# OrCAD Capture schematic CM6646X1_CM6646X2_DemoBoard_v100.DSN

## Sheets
1 01.HISTORY NOTE: title: HISTORY NOTE; rev: v100; company: C-MEDIA ELECTRONICS Inc.; note: CMA162A EVB; note: 6F., 100, Sec. 4, Civil Boulevard, Taipei, Taiwan, R.O.C.
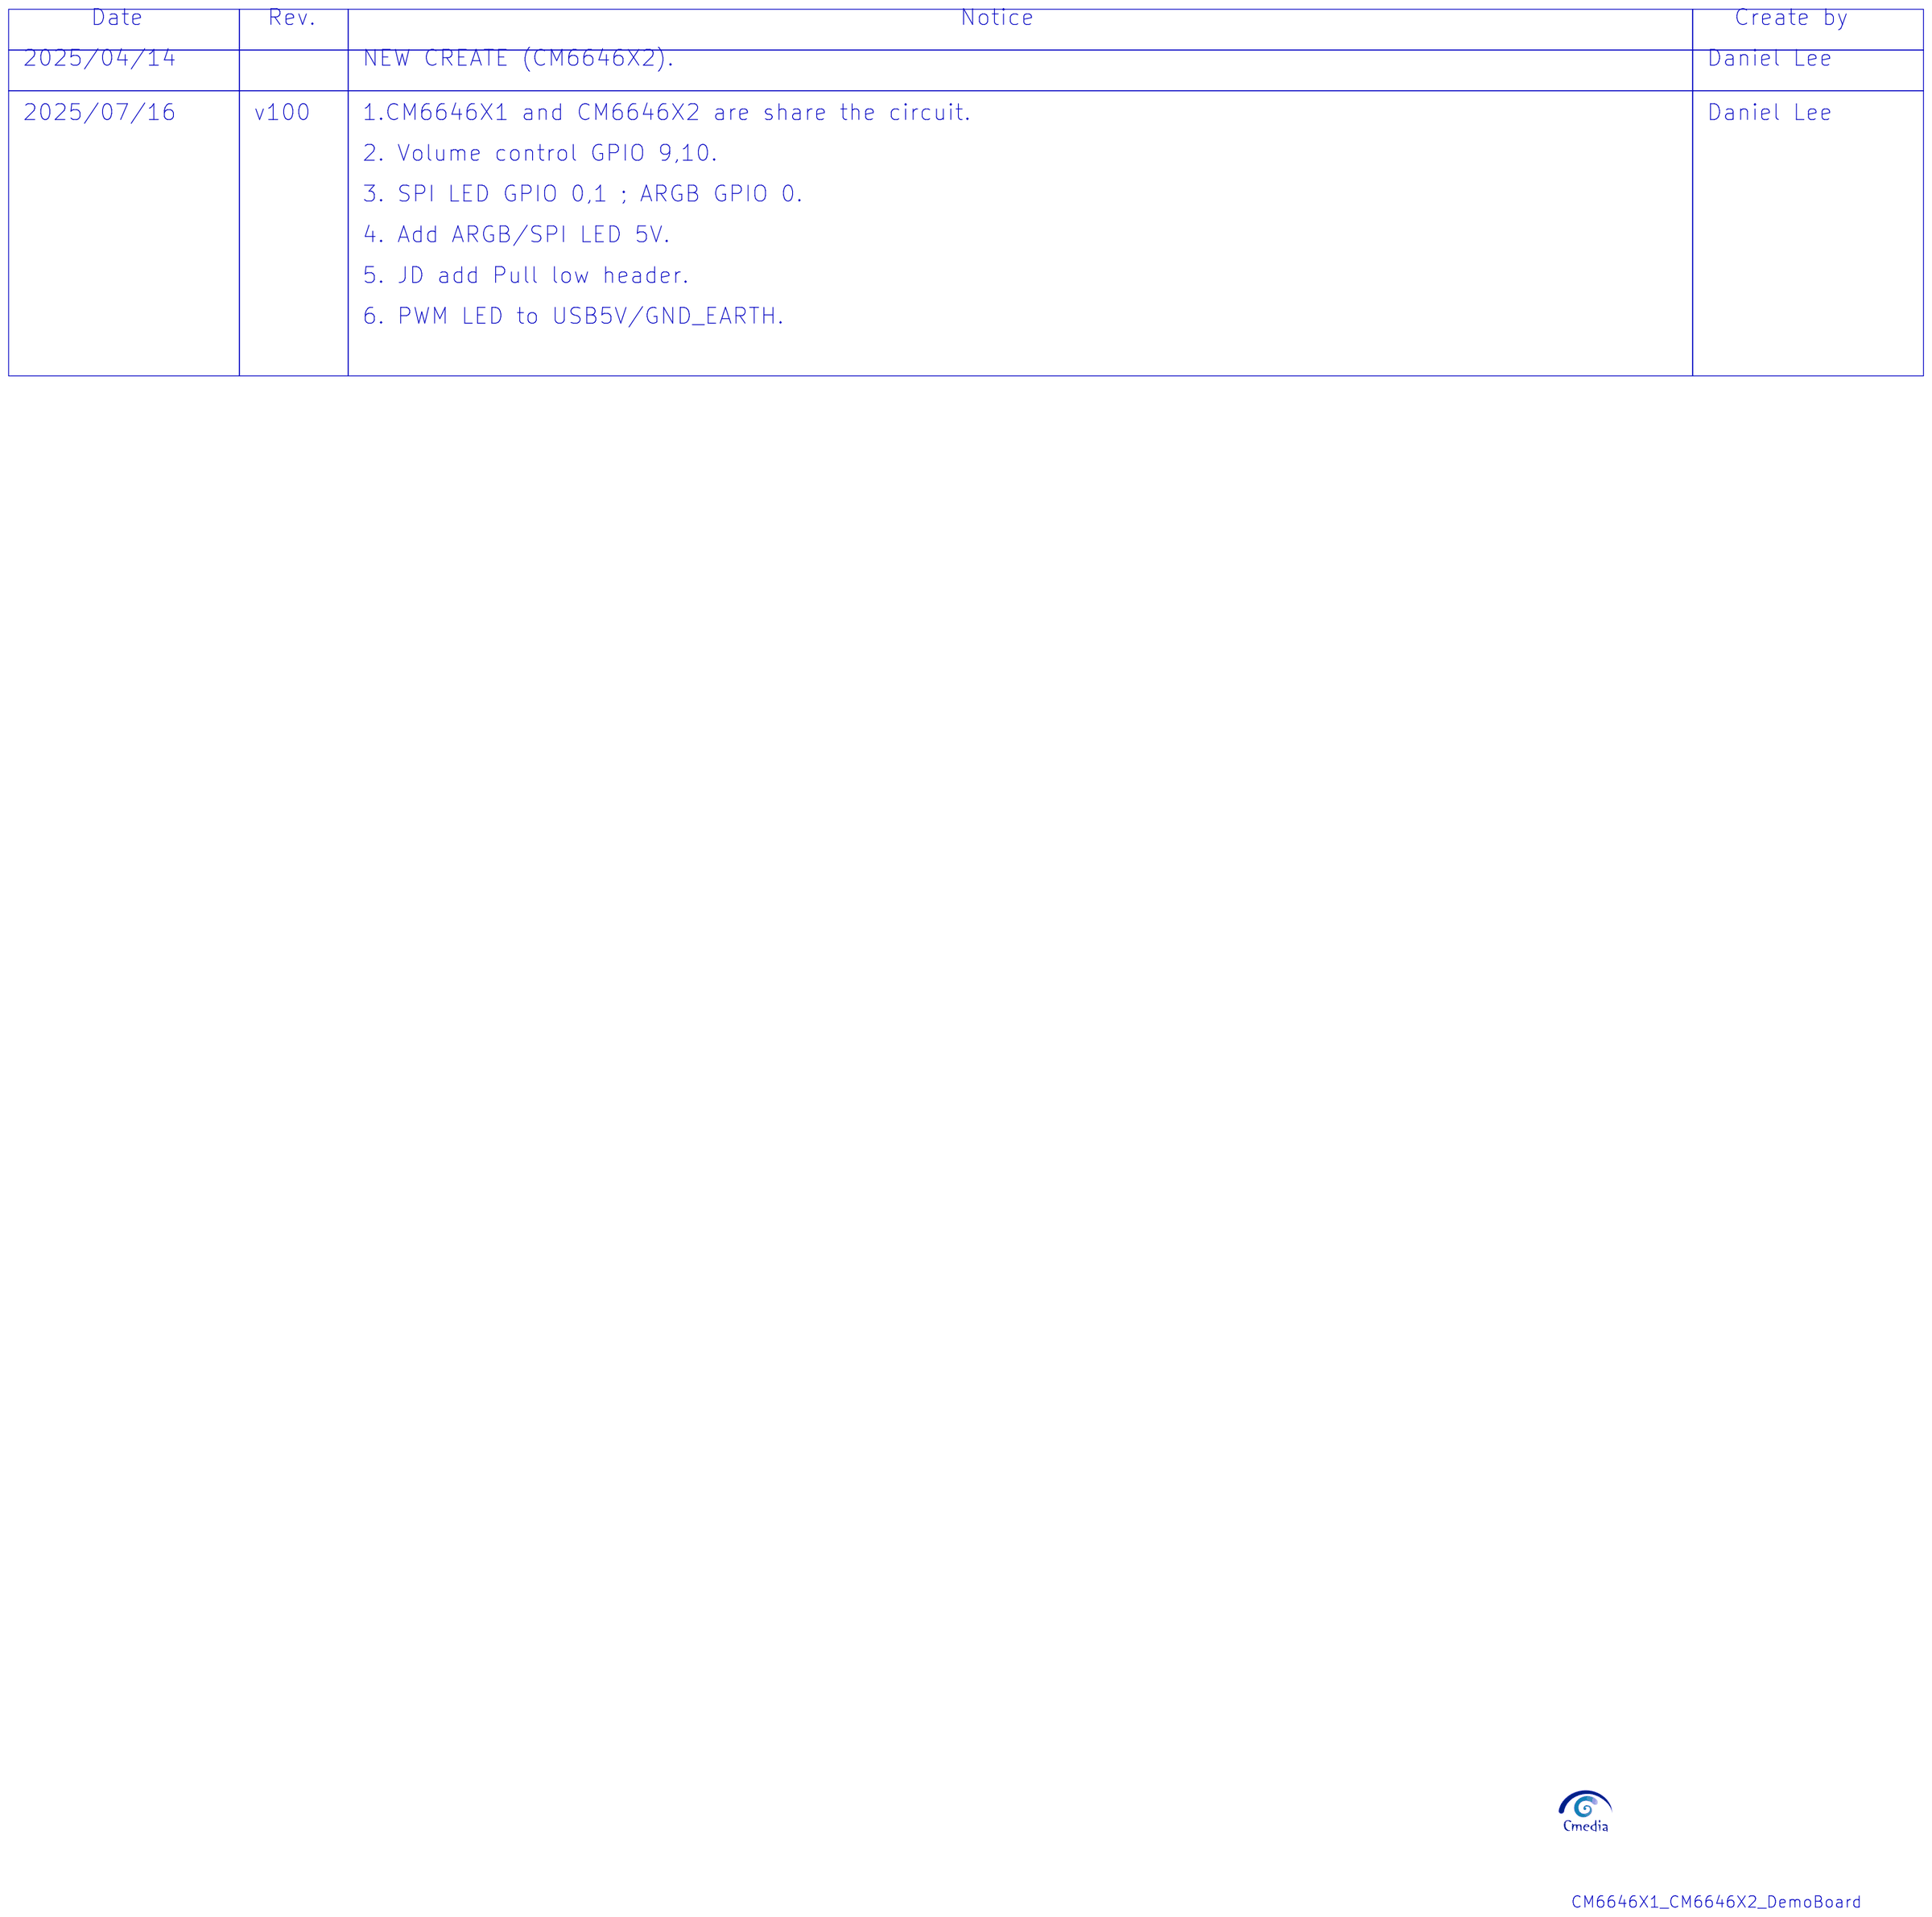
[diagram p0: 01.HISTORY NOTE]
2 02.FUNCTIONAL BLOCK DIAGRAM: title: CM6646X1_CM6646X2 DB FUNCTIONAL BLOCK
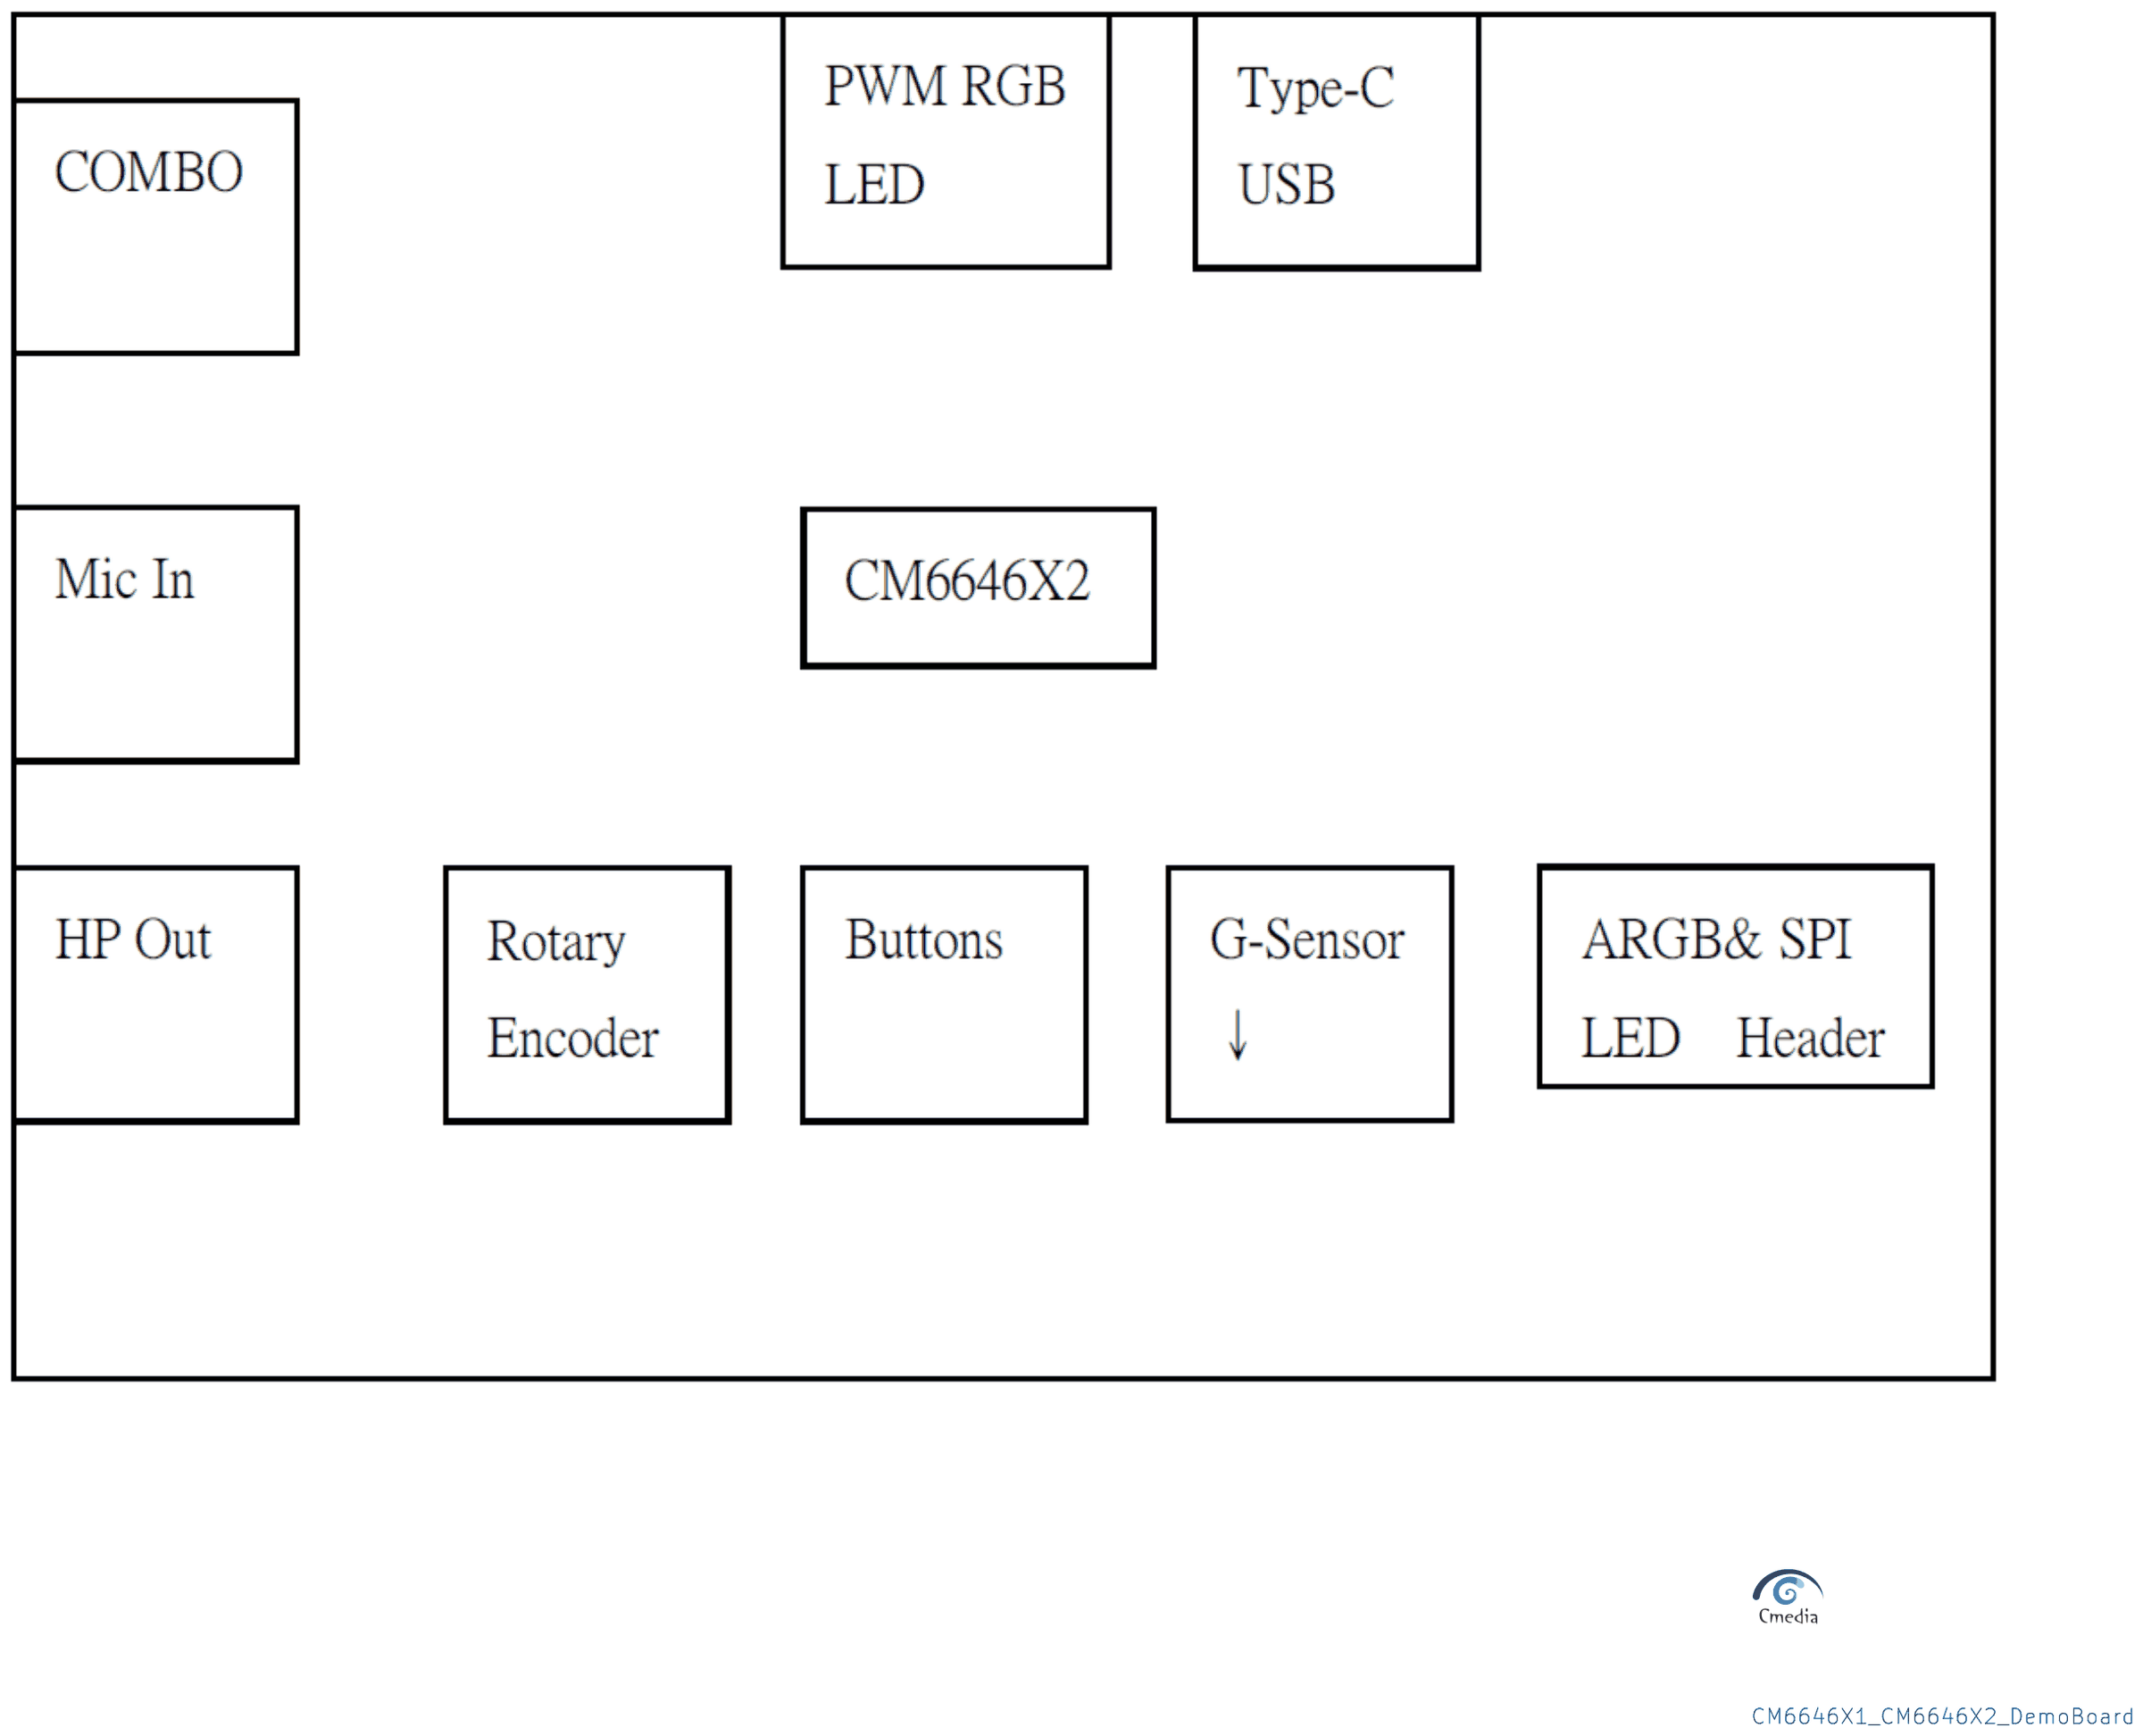
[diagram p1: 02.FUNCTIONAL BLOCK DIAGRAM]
3 03.PLACEMENT: title: Layout Placement
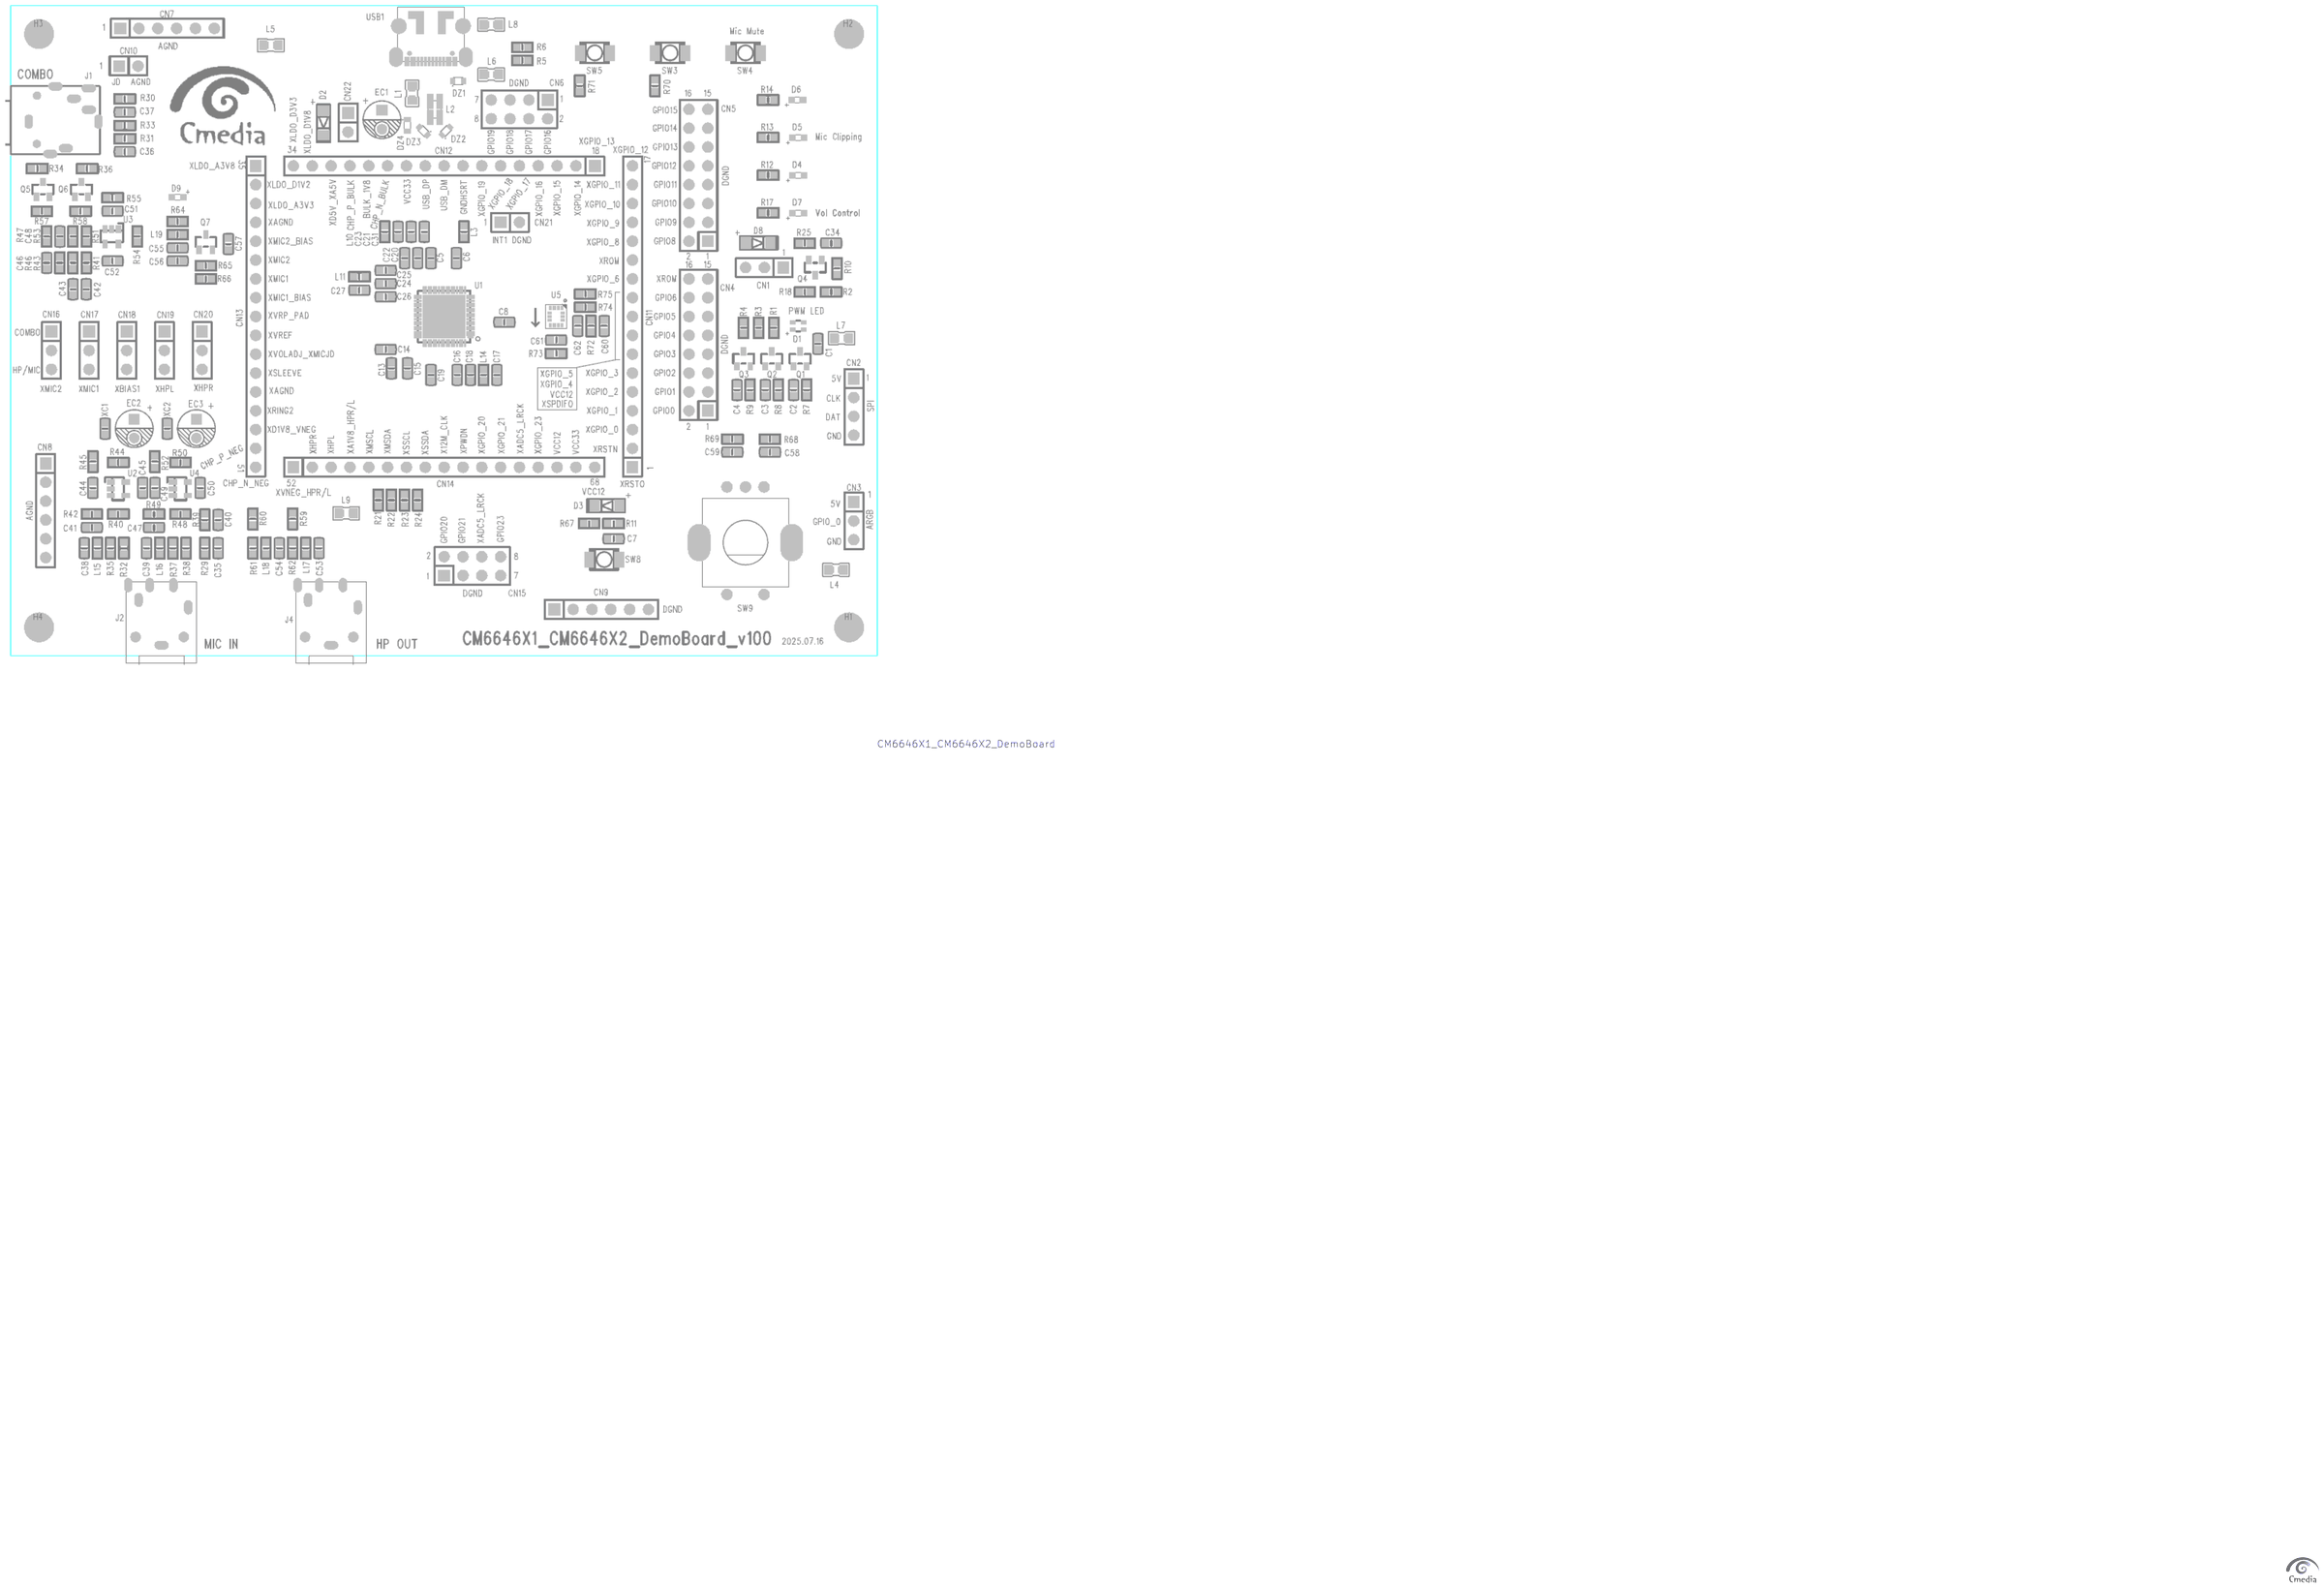
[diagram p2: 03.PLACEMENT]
4 04.CM6646X1_CM6646X2: size Custom; title: CM6646X1_CM6646X2 QFN-68; rev: v101
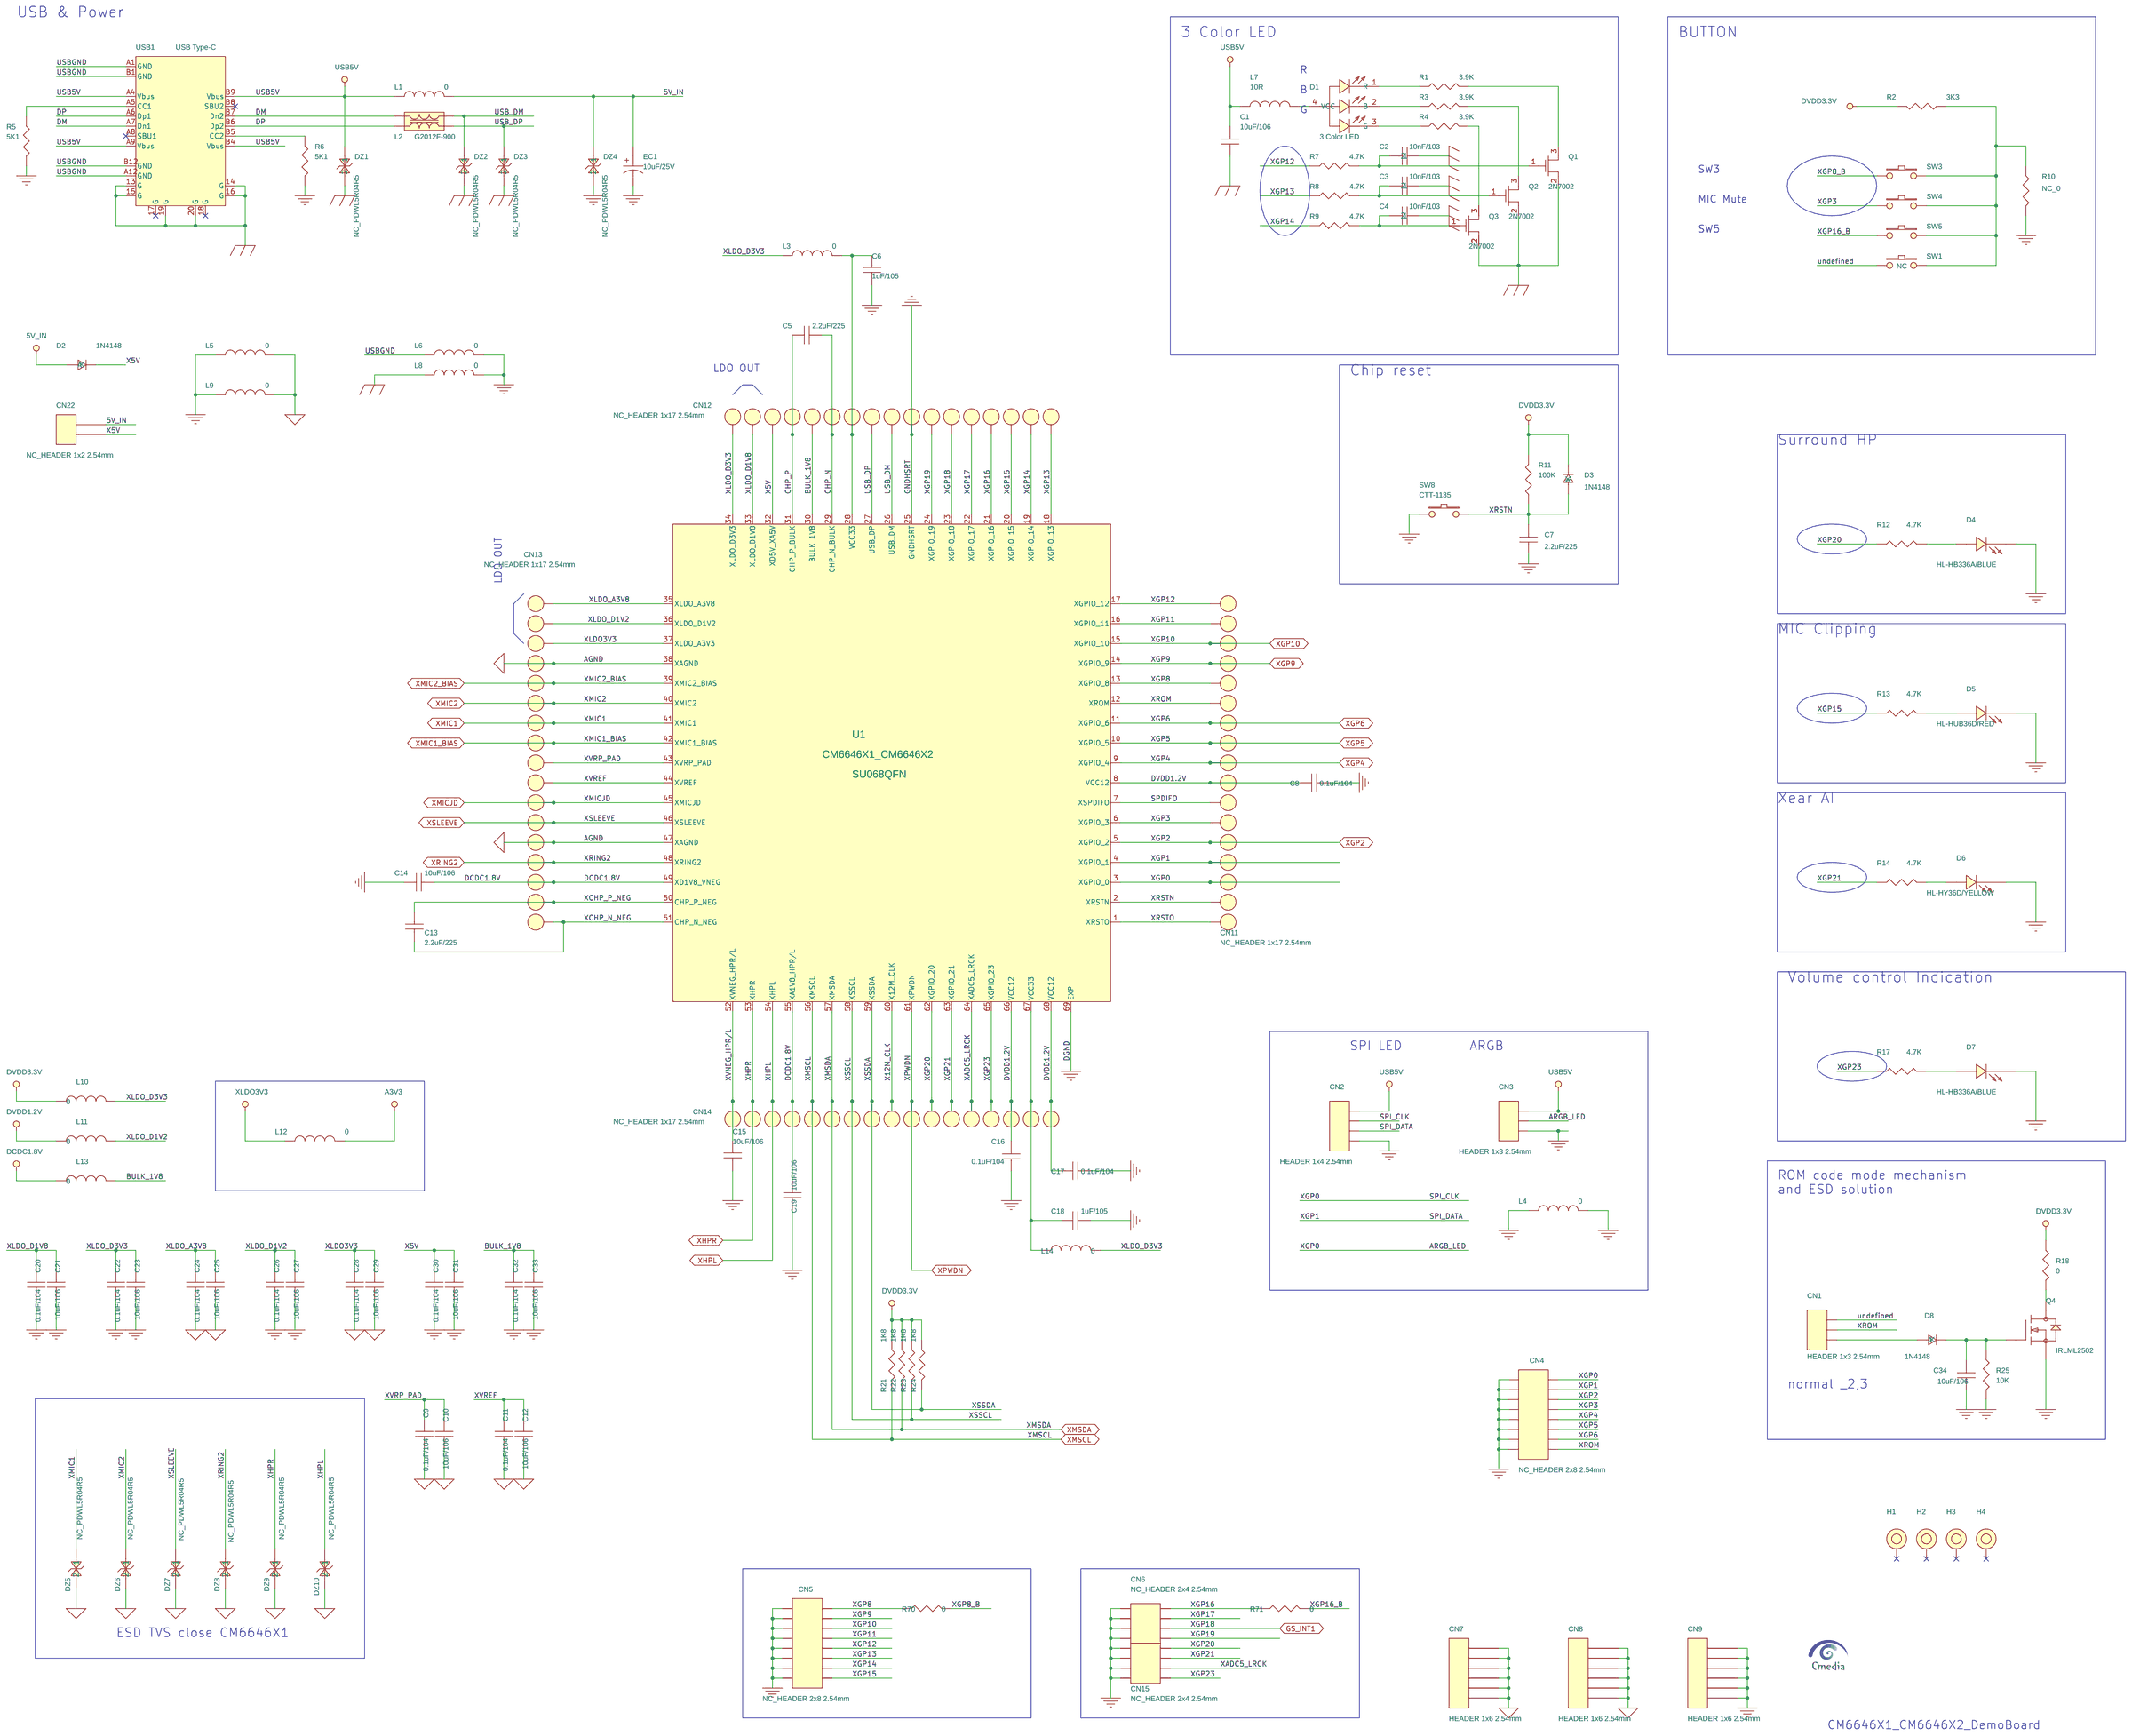
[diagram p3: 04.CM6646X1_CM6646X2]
5 05.G-Sensor: size A4; title: G-Sensor; note: CM6646X1_CM6646X2_DemoBoard
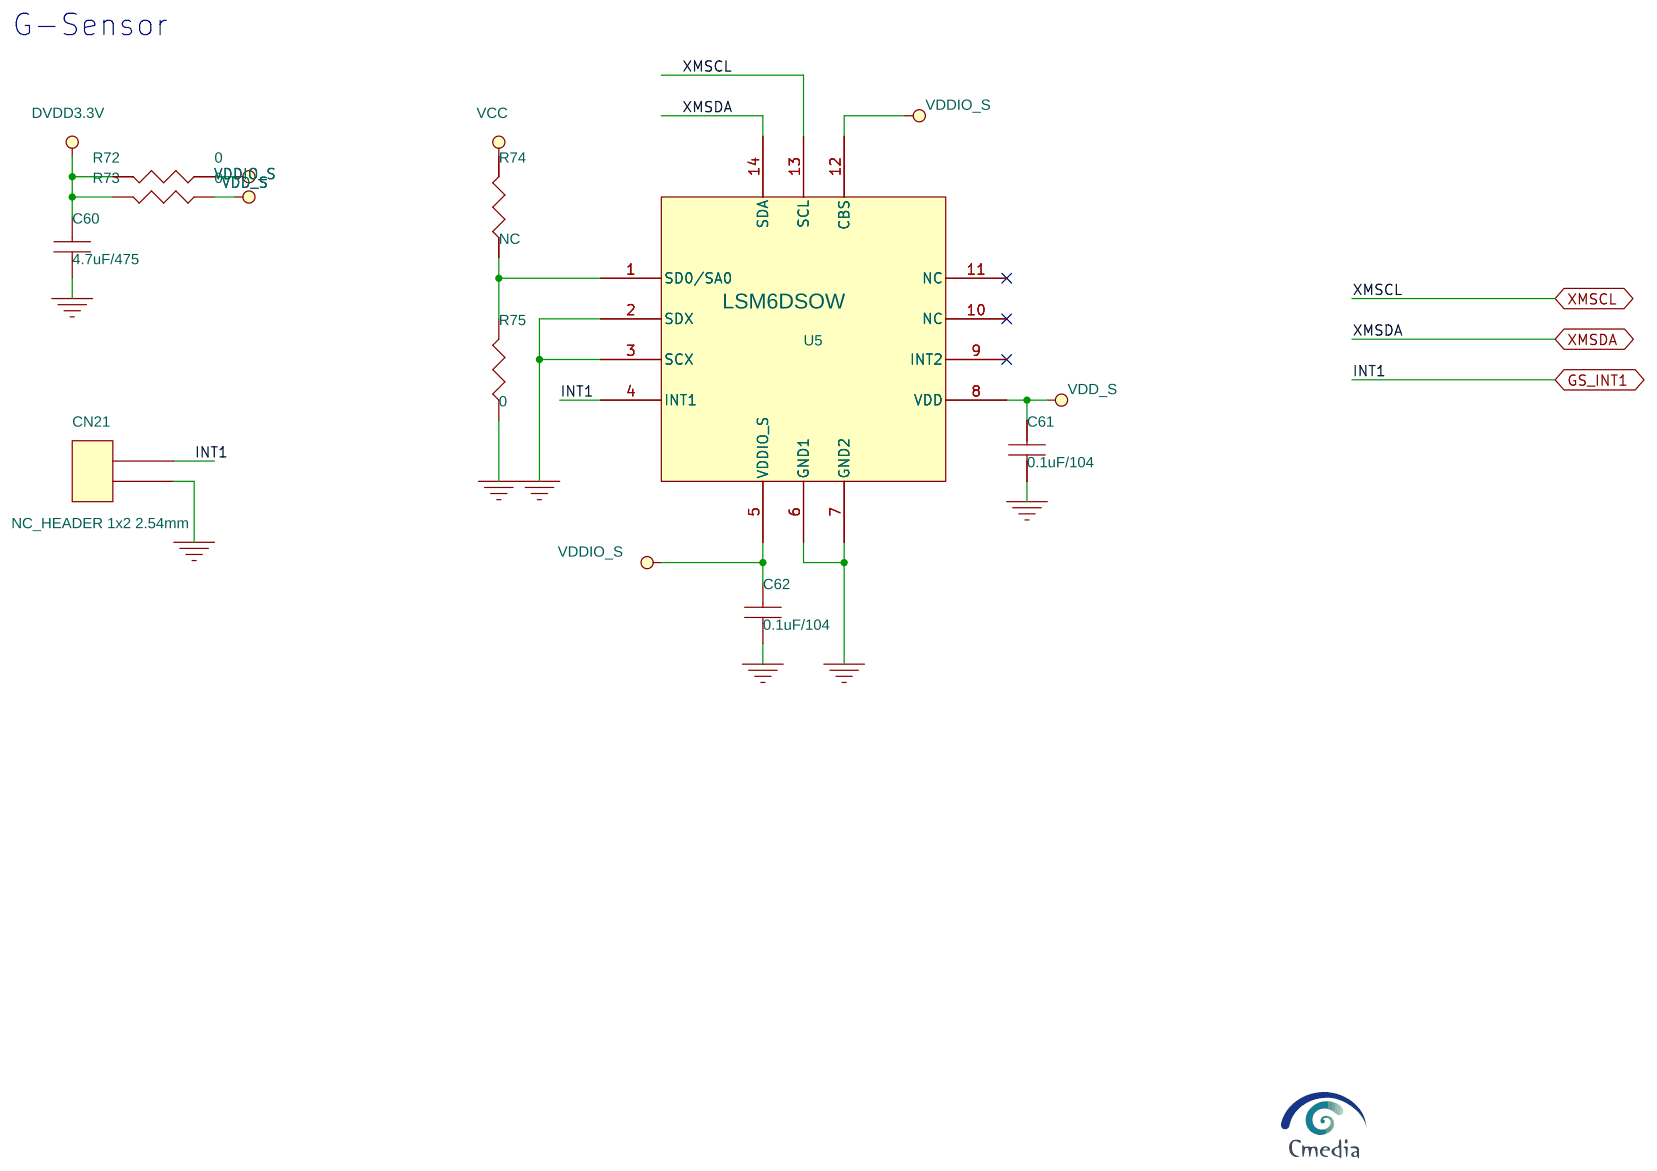
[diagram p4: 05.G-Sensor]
6 07.POWER: size B; title: OPA power and Encoder; rev: V100
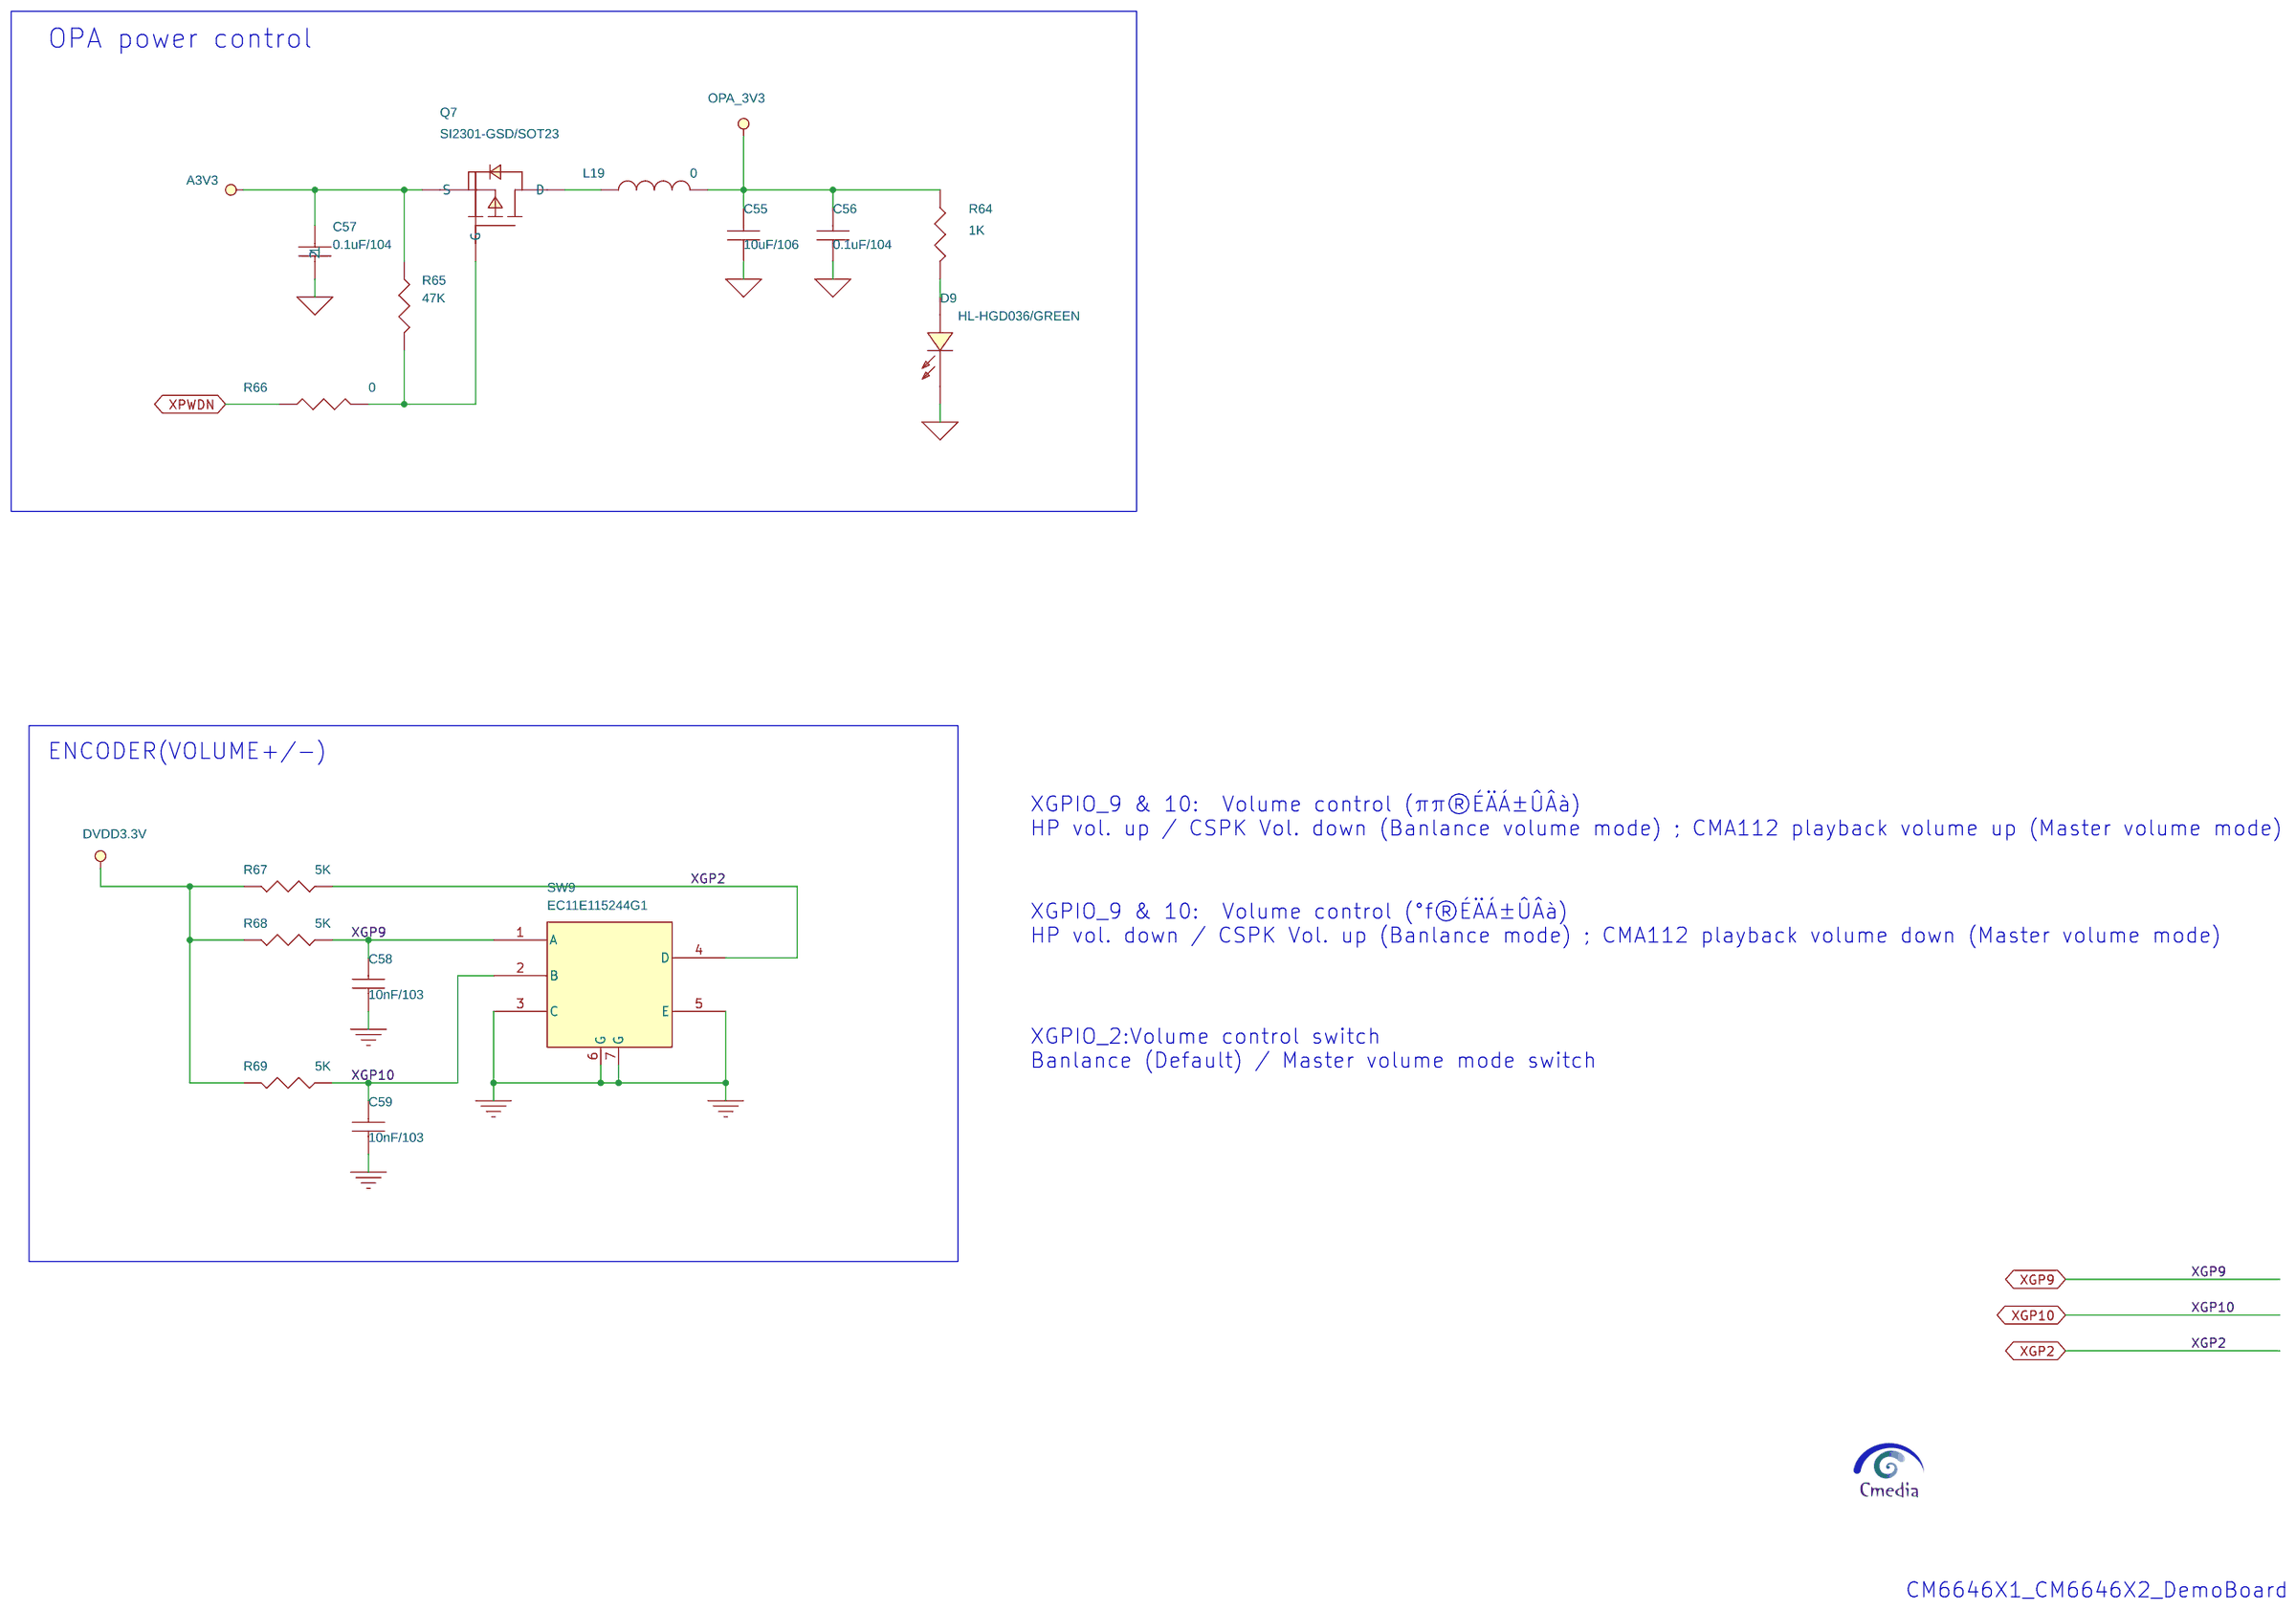
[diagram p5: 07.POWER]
7 06.ANALOG IN/OUT &COMBO JACK: size Custom; title: ANALOG IN/OUT &COMBO JACK; note: CM6646X1 Demoboard 68pin
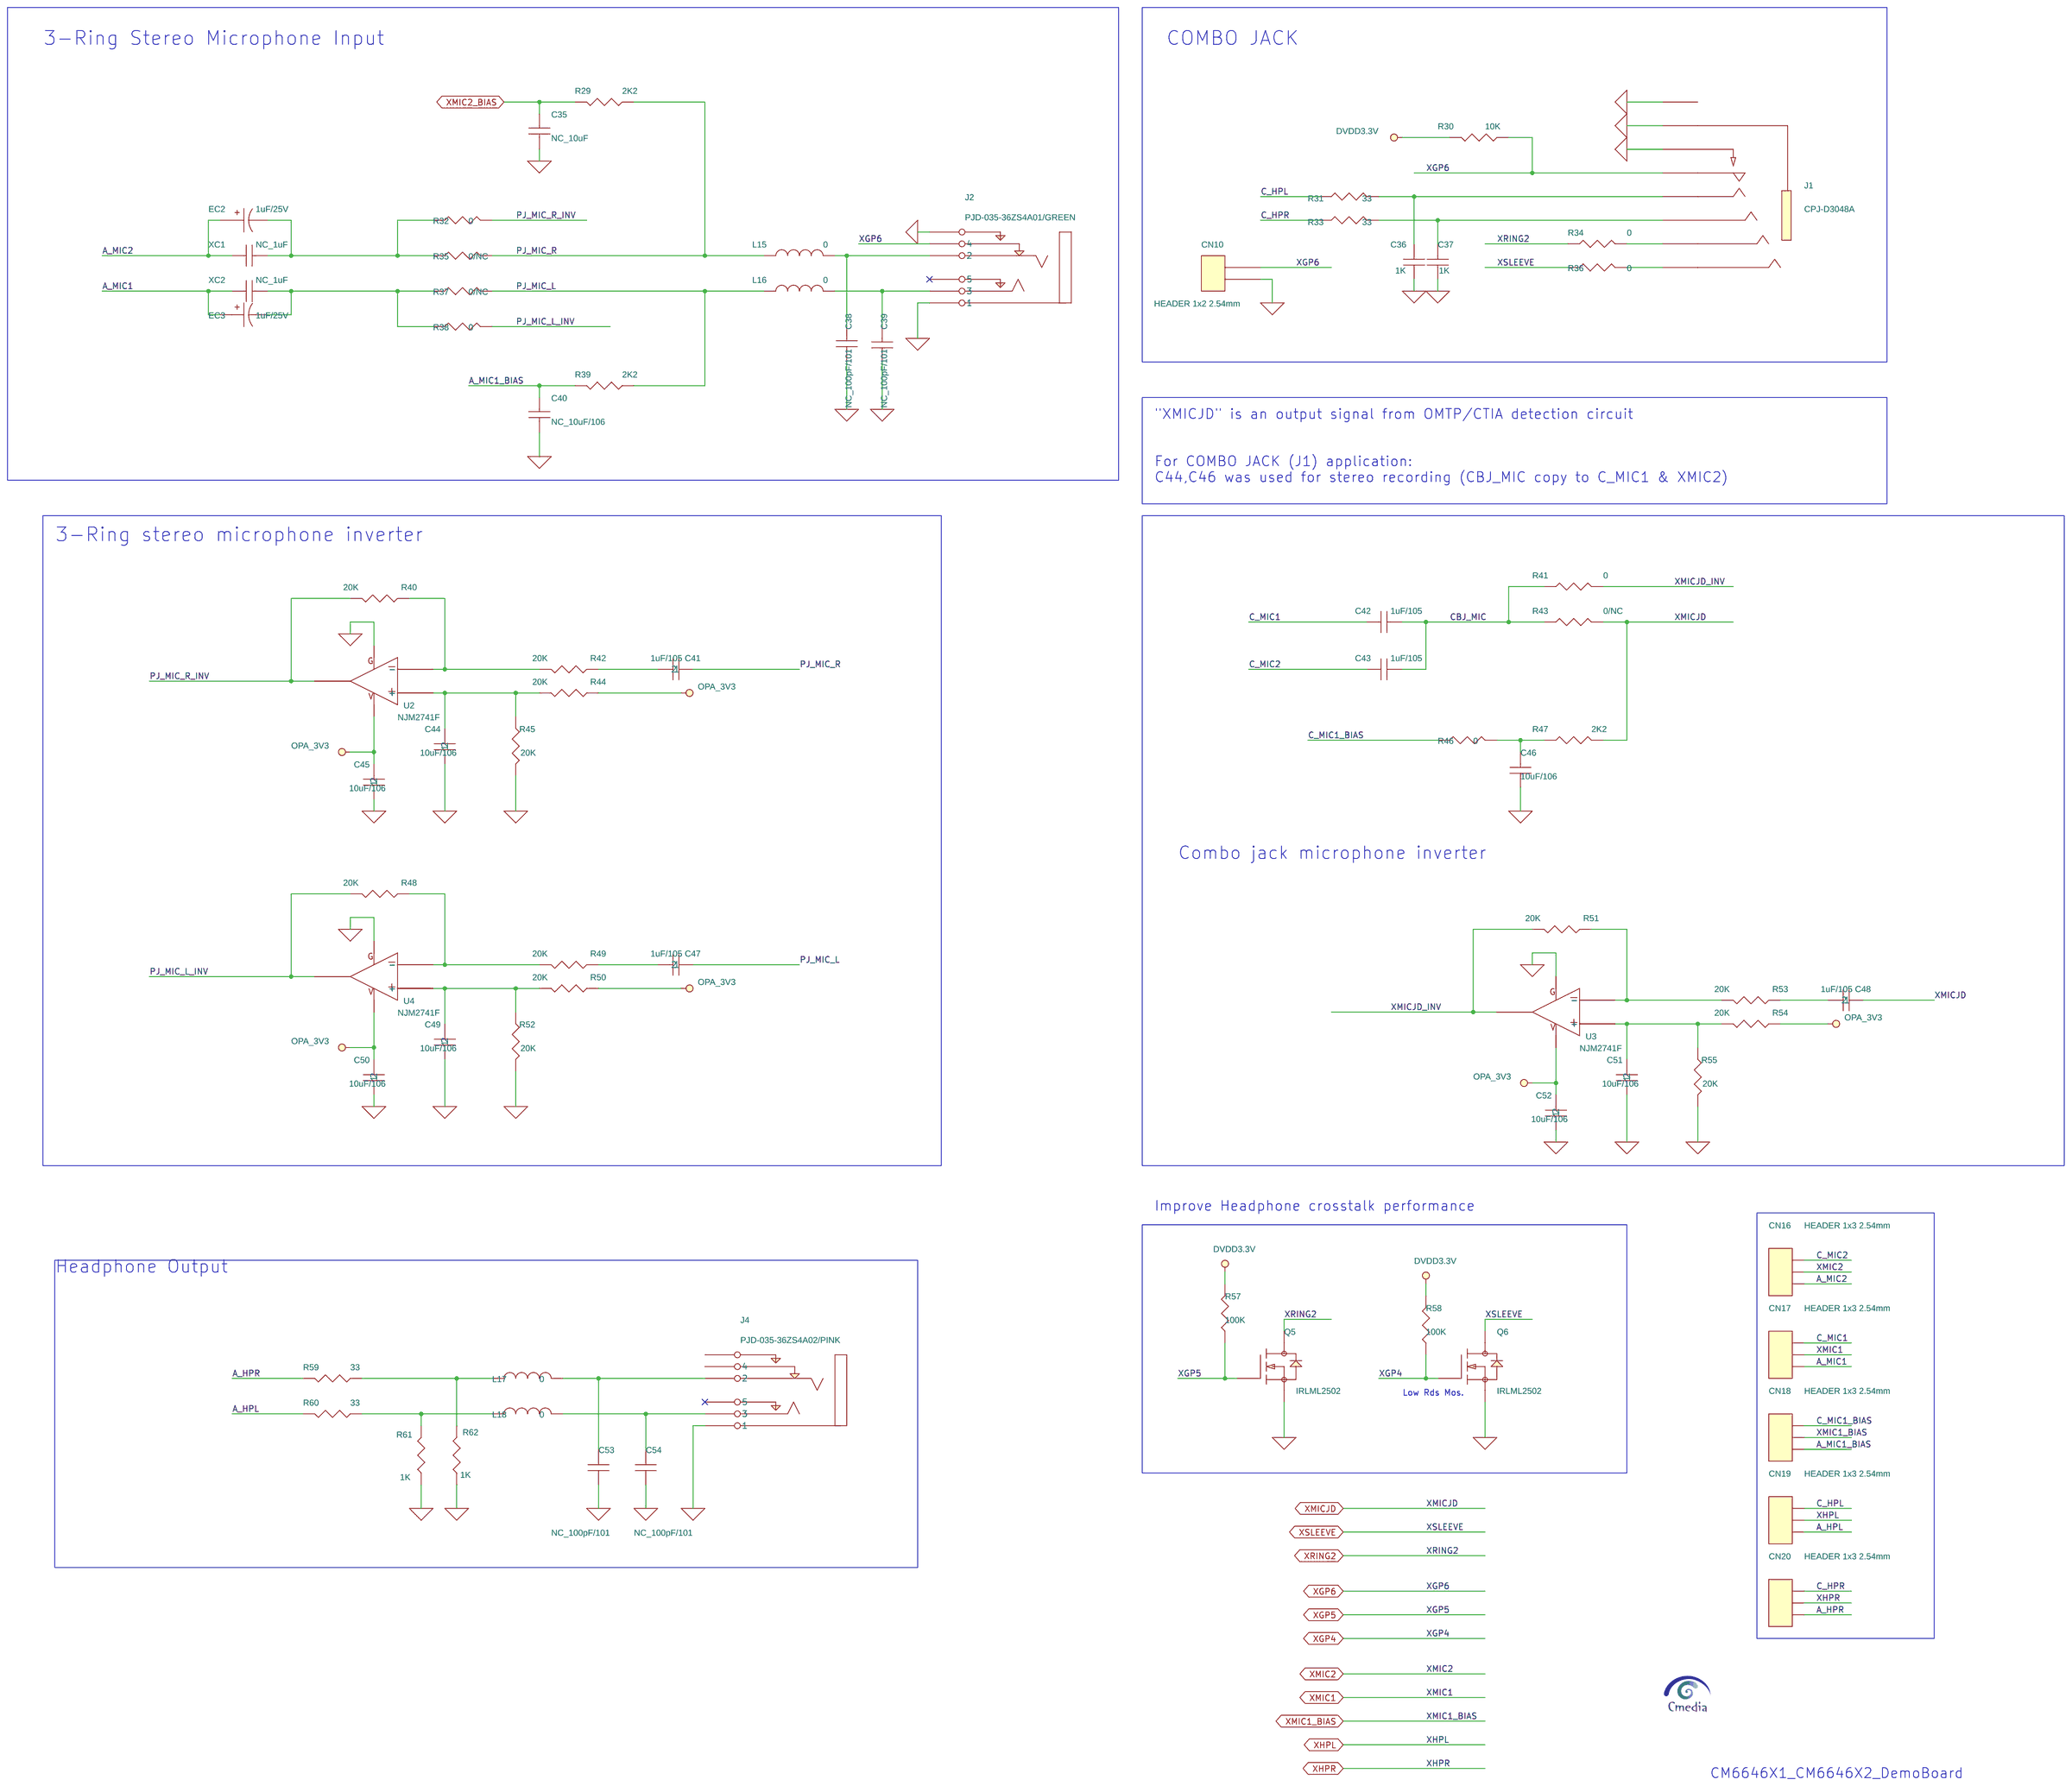
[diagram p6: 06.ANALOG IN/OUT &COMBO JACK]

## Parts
sheet 04.CM6646X1_CM6646X2
C1  10uF/106  [SC0603]
C2  10nF/103  [SC0603]
C3  10nF/103  [SC0603]
C4  10nF/103  [SC0603]
C5  2.2uF/225  [SC0603]
C6  1uF/105  [SC0603]
C7  2.2uF/225  [SC0603]
C8  0.1uF/104  [SC0603]
C9  0.1uF/104  [SC0603]
C10  10uF/106  [SC0603]
C11  0.1uF/104  [SC0603]
C12  10uF/106  [SC0603]
C13  2.2uF/225  [SC0603]
C14  10uF/106  [SC0603]
C15  10uF/106  [SC0603]
C16  0.1uF/104  [SC0603]
C17  0.1uF/104  [SC0603]
C18  1uF/105  [SC0603]
C19  10uF/106  [SC0603]
C20  0.1uF/104  [SC0603]
C21  10uF/106  [SC0603]
C22  0.1uF/104  [SC0603]
C23  10uF/106  [SC0603]
C24  0.1uF/104  [SC0603]
C25  10uF/106  [SC0603]
C26  0.1uF/104  [SC0603]
C27  10uF/106  [SC0603]
C28  0.1uF/104  [SC0603]
C29  10uF/106  [SC0603]
C30  0.1uF/104  [SC0603]
C31  10uF/106  [SC0603]
C32  0.1uF/104  [SC0603]
C33  10uF/106  [SC0603]
C34  10uF/106  [SC0603]
CN1  HEADER 1x3 2.54mm  [J1A3]
CN2  HEADER 1x4 2.54mm  [J1A4]
CN3  HEADER 1x3 2.54mm  [J1A3]
CN4  NC_HEADER 2x8 2.54mm  [J2A8A]
CN5  NC_HEADER 2x8 2.54mm  [J2A8A]
CN6  NC_HEADER 2x4 2.54mm  [J2A4A]
CN7  HEADER 1x6 2.54mm  [J1A6]
CN8  HEADER 1x6 2.54mm  [J1A6]
CN9  HEADER 1x6 2.54mm  [J1A6]
CN11  NC_HEADER 1x17 2.54mm  [J1A17]
CN12  NC_HEADER 1x17 2.54mm  [J1A17]
CN13  NC_HEADER 1x17 2.54mm  [J1A17]
CN14  NC_HEADER 1x17 2.54mm  [J1A17]
CN15  NC_HEADER 2x4 2.54mm  [J2A4A]
CN22  NC_HEADER 1x2 2.54mm  [J1A2]
D1  3 Color LED  [SLED-HG197RGB]
D2  1N4148  [SD4148]
D3  1N4148  [SD4148]
D4  HL-HB336A/BLUE  [LED_HL-0603]
D5  HL-HUB36D/RED  [LED_HL-0603]
D6  HL-HY36D/YELLOW  [LED_HL-0603]
D7  HL-HB336A/BLUE  [LED_HL-0603]
D8  1N4148  [SD4148]
DZ1  NC_PDWL5R04R5  [SOD-523]
DZ2  NC_PDWL5R04R5  [SOD-523]
DZ3  NC_PDWL5R04R5  [SOD-523]
DZ4  NC_PDWL5R04R5  [SOD-523]
DZ5  NC_PDWL5R04R5  [SOD-523]
DZ6  NC_PDWL5R04R5  [SOD-523]
DZ7  NC_PDWL5R04R5  [SOD-523]
DZ8  NC_PDWL5R04R5  [SOD-523]
DZ9  NC_PDWL5R04R5  [SOD-523]
DZ10  NC_PDWL5R04R5  [SOD-523]
EC1  10uF/25V  [DC100C5]
H1  T POINT R_0  [HOLE4.0]
H2  T POINT R_0  [HOLE4.0]
H3  T POINT R_0  [HOLE4.0]
H4  T POINT R_0  [HOLE4.0]
L1  0  [SL08050603]
L2  G2012F-900  [G2012F]
L3  0  [SR0603]
L4  0  [SL08050603]
L5  0  [SL08050603]
L6  0  [SL08050603]
L7  10R  [SL08050603]
L8  0  [SL08050603]
L9  0  [SL08050603]
L10  0  [SR0603]
L11  0  [SR0603]
L12  0  [SR0603]
L13  0  [SR0603]
L14  0  [SR0603]
Q1  2N7002  [SOT-23]
Q2  2N7002  [SOT-23]
Q3  2N7002  [SOT-23]
Q4  IRLML2502  [SOT-23-GDS]
R1  3.9K  [SR0603]
R2  3K3  [SR0603]
R3  3.9K  [SR0603]
R4  3.9K  [SR0603]
R5  5K1  [SR0603]
R6  5K1  [SR0603]
R7  4.7K  [SR0603]
R8  4.7K  [SR0603]
R9  4.7K  [SR0603]
R10  NC_0  [SR0603]
R11  100K  [SR0603]
R12  4.7K  [SR0603]
R13  4.7K  [SR0603]
R14  4.7K  [SR0603]
R17  4.7K  [SR0603]
R18  0  [SR0603]
R21  1K8  [SR0603]
R22  1K8  [SR0603]
R23  1K8  [SR0603]
R24  1K8  [SR0603]
R25  10K  [SR0603]
R70  0  [SR0603]
R71  0  [SR0603]
SW1  NC  [STSW-1135]
SW3  CTT-1135  [STSW-1135]
SW4  CTT-1135  [STSW-1135]
SW5  CTT-1135  [STSW-1135]
SW8  CTT-1135  [STSW-1135]
U1  CM6646X1_CM6646X2  [SU068QFN]
USB1  USB Type-C  [TUSB31CF-073-L-SMD]
sheet 05.G-Sensor
C60  4.7uF/475  [SC0603]
C61  0.1uF/104  [SC0603]
C62  0.1uF/104  [SC0603]
CN21  NC_HEADER 1x2 2.54mm  [J1A2]
R72  0  [SR0603]
R73  0  [SR0603]
R74  NC  [SR0603]
R75  0  [SR0603]
U5  LSM6DSOW  [LSM6DSD]
sheet 06.ANALOG IN/OUT &COMBO JACK
C35  NC_10uF  [SC0603]
C36  1K  [SC0603]
C37  1K  [SC0603]
C38  NC_100pF/101  [SC0603]
C39  NC_100pF/101  [SC0603]
C40  NC_10uF/106  [SC0603]
C41  1uF/105  [SC0603]
C42  1uF/105  [SC0603]
C43  1uF/105  [SC0603]
C44  10uF/106  [SC0603]
C45  10uF/106  [SC0603]
C46  10uF/106  [SC0603]
C47  1uF/105  [SC0603]
C48  1uF/105  [SC0603]
C49  10uF/106  [SC0603]
C50  10uF/106  [SC0603]
C51  10uF/106  [SC0603]
C52  10uF/106  [SC0603]
C53  NC_100pF/101  [SC0603]
C54  NC_100pF/101  [SC0603]
CN10  HEADER 1x2 2.54mm  [J1A2]
CN16  HEADER 1x3 2.54mm  [J1A3]
CN17  HEADER 1x3 2.54mm  [J1A3]
CN18  HEADER 1x3 2.54mm  [J1A3]
CN19  HEADER 1x3 2.54mm  [J1A3]
CN20  HEADER 1x3 2.54mm  [J1A3]
EC2  1uF/25V  [DC100C5]
EC3  1uF/25V  [DC100C5]
J1  CPJ-D3048A  [CPJ-D3048A]
J2  PJD-035-36ZS4A01/GREEN  [PJD-035-36ZS4A]
J4  PJD-035-36ZS4A02/PINK  [PJD-035-36ZS4A]
L15  0  [SR0603]
L16  0  [SR0603]
L17  0  [SR0603]
L18  0  [SR0603]
Q5  IRLML2502  [SOT-23-GDS]
Q6  IRLML2502  [SOT-23-GDS]
R29  2K2  [SR0603]
R30  10K  [SR0603]
R31  33  [SR0603]
R32  0  [SR0603]
R33  33  [SR0603]
R34  0  [SR0603]
R35  0/NC  [SR0603]
R36  0  [SR0603]
R37  0/NC  [SR0603]
R38  0  [SR0603]
R39  2K2  [SR0603]
R40  20K  [SR0603]
R41  0  [SR0603]
R42  20K  [SR0603]
R43  0/NC  [SR0603]
R44  20K  [SR0603]
R45  20K  [SR0603]
R46  0  [SR0603]
R47  2K2  [SR0603]
R48  20K  [SR0603]
R49  20K  [SR0603]
R50  20K  [SR0603]
R51  20K  [SR0603]
R52  20K  [SR0603]
R53  20K  [SR0603]
R54  20K  [SR0603]
R55  20K  [SR0603]
R57  100K  [SR0603]
R58  100K  [SR0603]
R59  33  [SR0603]
R60  33  [SR0603]
R61  1K  [SR0603]
R62  1K  [SR0603]
U2  NJM2741F  [SOT23-5]
U3  NJM2741F  [SOT23-5]
U4  NJM2741F  [SOT23-5]
XC1  NC_1uF  [SC0603]
XC2  NC_1uF  [SC0603]
sheet 07.POWER
C55  10uF/106  [SC0603]
C56  0.1uF/104  [SC0603]
C57  0.1uF/104  [SC0603]
C58  10nF/103  [SC0603]
C59  10nF/103  [SC0603]
D9  HL-HGD036/GREEN  [LED_HL-0603]
L19  0  [SR0603]
Q7  SI2301-GSD/SOT23  [SOT-23]
R64  1K  [SR0603]
R65  47K  [SR0603]
R66  0  [SR0603]
R67  5K  [SR0603]
R68  5K  [SR0603]
R69  5K  [SR0603]
SW9  EC11E115244G1  [EC11E115244G1]

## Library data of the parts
C1 XC1 = CAP_NP_11
C2 C50 = C_1
C3 C52 C57 = C
C4 C41 = C_2
C5 C43 = CAP_NP_6
C6 = CAP_NP_28
C7 = CAP_NP_26
C8 C37 = CAP_NP_12
C9 = CAP_NP_14
C10 = CAP_NP_24
C11 = CAP_NP_22
C12 C39 = CAP_NP_9
C13 = CAP_NP_17
C14 C53 C58 C60 = CAP_NP
C15 C36 C55 = CAP_NP_3
C16 C35 = CAP_NP_7
C17 = CAP_NP_29
C18 C38 C59 C62 = CAP_NP_2
C19 C54 = CAP_NP_8
C20 C40 = CAP_NP_5
C21 = CAP_NP_20
C22 C46 = CAP_NP_4
C23 = CAP_NP_19
C24 C42 C56 C61 = CAP_NP_1
C25 = CAP_NP_18
C26 = CAP_NP_30
C27 DZ3 = CAP_NP_16
C28 = CAP_NP_27
C29 = CAP_NP_15
C30 = CAP_NP_25
C31 = CAP_NP_13
C32 = CAP_NP_23
C33 XC2 = CAP_NP_10
C34 = CAP_NP_21
CN1 CN3 CN16-CN20 = HEADER_5_19
CN2 = HEADER_5_24
CN4 CN5 = HEADER_5X2_19
CN6 CN15 = HEADER_5X2_25
CN7-CN9 = HEADER_5_18
CN11-CN14 = HEADER_54x2_SM_12
CN10 CN21 CN22 = HEADER_5_22
D1 = LED_2
D2 D3 D8 = 1N4376_0
D4-D7 D9 = LED
DZ1 = CAP_NP_16_1
DZ2 = CAP_NP_16_6
DZ4 = CAP_NP_16_5
DZ5 = CAP_NP_16_4
DZ6 = CAP_NP_16_9
DZ7 = CAP_NP_16_3
DZ8 = CAP_NP_16_8
DZ9 = CAP_NP_16_2
DZ10 = CAP_NP_16_7
EC1-EC3 = CAPACITOR_POL
H1-H4 = T_POINT_R_4
L1 L3-L19 = INDUCTOR
L2 = INDUCTOR_3
Q1-Q3 = NPN_BCE_4
Q4-Q6 = 2N7002
R1-R4 R7-R14 R17 R18 R21-R25 R29-R39 R41 R43 R46 R47 R57-R62 R64-R75 = R
R5 R6 = R_2
SW1 SW3-SW5 = SW_PUSHBUTTON
SW8 = SW_PUSHBUTTON: 1ST PART FIELD: WAKE UP
U1 = CMI120_70
USB1 = HEADER_4_2: 1ST PART FIELD: USB Micro B-Type SMD
U5 = CMI120_34
C44 = C_8
C45 U2-U4 = C_5
C47 = C_4
C48 = C_3
C49 = C_7
C51 = C_6
J1 = PHONEJACK_STEREO_SW_12_v2
J2 J4 = PHONEJACK_STEREO_SW_12: 1ST PART FIELD: MIC
R40 R42 R44 R45 R48-R55 = R_0
Q7 = BSH201_7
SW9 = X72011_7

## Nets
5V_IN: CN22.1 D2.1(A) DZ4.1 EC1.1 L1.1
A3V3: C57.1 L12.2 Q7.2(S) R65.1
AGND: C9.2 C10.2 C11.2 C12.2 C24.2 C25.2 C28.2 C29.2 C35.2 C36.1 C37.1 C38.2 C39.1 C40.2 C44.1 C45.1 C46.1 C49.1 C50.1 C51.1 C52.1 C53.1 C54.1 C55.1 C56.1 C57.2 CN7.1 CN7.2 CN7.3 CN7.4 CN7.5 CN7.6 CN8.1 CN8.2 CN8.3 CN8.4 CN8.5 CN8.6 CN10.2 CN13.4 CN13.13 D9.2(CATHODE) DZ5.2 DZ6.2 DZ7.2 DZ8.2 DZ9.2 DZ10.2 J1.5 J1.7 J1.8 J2.1 J2.6 J4.1 L5.2 L9.2 Q5.2(SOURCE) Q6.2(SOURCE) R45.1 R52.1 R55.1 R61.1 R62.1 U1.38(XAGND) U1.47(XAGND) U2.2 U3.2 U4.2
DGND: C6.2 C7.1 C8.2 C14.1 C15.2 C16.1 C17.2 C18.2 C19.2 C20.2 C21.2 C22.2 C23.2 C26.2 C27.2 C30.2 C31.2 C32.2 C33.2 C34.1 C58.2 C59.2 C60.2 C61.2 C62.2 CN4.1 CN4.3 CN4.5 CN4.7 CN4.9 CN4.11 CN4.13 CN4.15 CN5.1 CN5.3 CN5.5 CN5.7 CN5.9 CN5.11 CN5.13 CN5.15 CN6.1 CN6.3 CN6.5 CN6.7 CN9.1 CN9.2 CN9.3 CN9.4 CN9.5 CN9.6 CN12.8 CN15.1 CN15.3 CN15.5 CN15.7 CN21.2 D4.2(CATHODE) D5.2(CATHODE) D6.2(CATHODE) D7.2(CATHODE) DZ4.2 EC1.2 L4.1 L5.1 L6.2 L8.2 L9.1 Q4.2(SOURCE) R5.1 R6.1 R10.2 R25.2 R75.1 SW8.2 SW9.3(C) SW9.5(E) SW9.6(G) SW9.7(G) U1.25(GNDHSRT) U1.69(EXP) U5.2(SDX) U5.3(SCX) U5.6(GND1) U5.7(GND2)
DVDD1.2V: C8.1 C16.2 C17.1 CN11.8 CN14.15 CN14.17 L11.1 U1.8(VCC12) U1.66(VCC12) U1.68(VCC12)
DVDD3.3V: C60.1 D3.2(K) L10.1 R2.2 R11.2 R18.1 R21.1 R22.1 R23.1 R24.1 R30.1 R57.2 R58.2 R67.1 R68.1 R69.1 R72.2 R73.2
GND_EARTH: C1.1 C2.1 C3.1 C4.1 DZ1.2 DZ2.2 DZ3.2 L8.1 Q1.2(S) Q2.2(S) Q3.2(S) USB1.13(G) USB1.14(G) USB1.15(G) USB1.16(G) USB1.19(G) USB1.20(G)
VDD_S: C61.1 R73.1 U5.8(VDD)
VDDIO_S: C62.1 R72.1 R74.2 U5.5(VDDIO_S) U5.12(CBS)
A_HPL: CN19.3 R60.2
A_HPR: CN20.3 R59.2
A_MIC1: CN17.3 EC3.1 XC2.1
A_MIC1_BIAS: C40.1 CN18.3 R39.2
A_MIC2: CN16.3 EC2.1 XC1.1
ARGB_LED: CN2.2 CN3.2 CN4.2 CN11.3 U1.3(XGPIO_0)
BULK_1V8: C32.1 C33.1 CN12.13 L13.2 U1.30(BULK_1V8)
C_HPL: CN19.1 R31.1
C_HPR: CN20.1 R33.1
C_MIC1: C42.1 CN17.1
C_MIC1_BIAS: CN18.1 R46.2
C_MIC2: C43.1 CN16.1
CBJ_MIC: C42.2 C43.2 R41.2 R43.2
CHP_N: C5.2 CN12.12 U1.29(CHP_N_BULK)
CHP_P: C5.1 CN12.14 U1.31(CHP_P_BULK)
DCDC1.8V: C14.2 C19.1 CN13.15 CN14.4 L13.1 U1.49(XD1V8_VNEG) U1.55(XA1V8_HPR/L)
DM: L2.3 USB1.A7(Dn1) USB1.B7(Dn2)
DP: L2.1 USB1.A6(Dp1) USB1.B6(Dp2)
GS_INT1: CN6.6 CN12.6 CN21.1 U1.23(XGPIO_18) U5.4(INT1)
LGND: CN2.4 CN3.3 L4.2
OPA_3V3: C45.2 C50.2 C52.2 C55.2 C56.2 L19.2 R44.2 R50.2 R54.2 R64.1 U2.5 U3.5 U4.5
PJ_MIC_L: C47.1 L16.1 R37.1 R39.1
PJ_MIC_L_INV: R38.1 R48.1 U4.4
PJ_MIC_R: C41.1 L15.1 R29.1 R35.1
PJ_MIC_R_INV: R32.1 R40.1 U2.4
SPDIFO: CN11.7 U1.7(XSPDIFO)
SPI_DATA: CN2.3 CN4.4 CN11.4 U1.4(XGPIO_1)
undefined: CN1.1 SW1.1
USB5V: C1.2 CN2.1 CN3.1 DZ1.1 L1.2 L7.1 USB1.A4(Vbus) USB1.A9(Vbus) USB1.B4(Vbus) USB1.B9(Vbus)
USB_DM: CN12.9 DZ2.1 L2.4 U1.26(USB_DM)
USB_DP: CN12.10 DZ3.1 L2.2 U1.27(USB_DP)
USBGND: L6.1 USB1.A1(GND) USB1.A12(GND) USB1.B1(GND) USB1.B12(GND)
X5V: C30.1 C31.1 CN12.15 CN22.2 D2.2(K) U1.32(XD5V_XA5V)
X12M_CLK: CN14.9 U1.60(X12M_CLK)
XADC5_LRCK: CN14.13 CN15.6 U1.64(XADC5_LRCK)
XCHP_N_NEG: C13.2 CN13.17 U1.51(CHP_N_NEG)
XCHP_P_NEG: C13.1 CN13.16 U1.50(CHP_P_NEG)
XGP2: CN4.6 CN11.5 R67.2 SW9.4(D) U1.5(XGPIO_2)
XGP3: CN4.8 CN11.6 SW4.1 U1.6(XGPIO_3)
XGP4: CN4.10 CN11.9 Q6.1(GATE) R58.1 U1.9(XGPIO_4)
XGP5: CN4.12 CN11.10 Q5.1(GATE) R57.1 U1.10(XGPIO_5)
XGP6: CN4.14 CN10.1 CN11.11 J1.4 J2.4 R30.2 U1.11(XGPIO_6)
XGP8: CN5.2 CN11.13 R70.2 U1.13(XGPIO_8)
XGP8_B: R70.1 SW3.1
XGP9: C58.1 CN5.4 CN11.14 R68.2 SW9.1(A) U1.14(XGPIO_9)
XGP10: C59.1 CN5.6 CN11.15 R69.2 SW9.2(B) U1.15(XGPIO_10)
XGP11: CN5.8 CN11.16 U1.16(XGPIO_11)
XGP12: CN5.10 CN11.17 R7.1 U1.17(XGPIO_12)
XGP13: CN5.12 CN12.1 R8.1 U1.18(XGPIO_13)
XGP14: CN5.14 CN12.2 R9.1 U1.19(XGPIO_14)
XGP15: CN5.16 CN12.3 R13.1 U1.20(XGPIO_15)
XGP16: CN6.2 CN12.4 R71.2 U1.21(XGPIO_16)
XGP16_B: R71.1 SW5.1
XGP17: CN6.4 CN12.5 U1.22(XGPIO_17)
XGP19: CN6.8 CN12.7 U1.24(XGPIO_19)
XGP20: CN14.11 CN15.2 R12.1 U1.62(XGPIO_20)
XGP21: CN14.12 CN15.4 R14.1 U1.63(XGPIO_21)
XGP23: CN14.14 CN15.8 R17.1 U1.65(XGPIO_23)
XHPL: CN14.3 CN19.2 DZ10.1 U1.54(XHPL)
XHPR: CN14.2 CN20.2 DZ9.1 U1.53(XHPR)
XLDO3V3: C28.1 C29.1 CN13.3 L12.1 U1.37(XLDO_A3V3)
XLDO_A3V8: C24.1 C25.1 CN13.1 U1.35(XLDO_A3V8)
XLDO_D1V2: C26.1 C27.1 CN13.2 L11.2 U1.36(XLDO_D1V2)
XLDO_D1V8: C20.1 C21.1 CN12.16 U1.33(XLDO_D1V8)
XLDO_D3V3: C22.1 C23.1 CN12.17 L3.1 L10.2 L14.2 U1.34(XLDO_D3V3)
XMIC1: CN13.7 CN17.2 DZ5.1 U1.41(XMIC1)
XMIC1_BIAS: CN13.8 CN18.2 U1.42(XMIC1_BIAS)
XMIC2: CN13.6 CN16.2 DZ6.1 U1.40(XMIC2)
XMIC2_BIAS: C35.1 CN13.5 R29.2 U1.39(XMIC2_BIAS)
XMICJD: C48.1 CN13.11 R43.1 R47.1 U1.45(XMICJD)
XMICJD_INV: R41.1 R51.1 U3.4
XMSCL: CN14.5 R21.2 U1.56(XMSCL) U5.13(SCL)
XMSDA: CN14.6 R22.2 U1.57(XMSDA) U5.14(SDA)
XPWDN: CN14.10 R66.1 U1.61(XPWDN)
XRING2: CN13.14 DZ8.1 Q5.3(DRAIN) R34.1 U1.48(XRING2)
XROM: CN1.2 CN4.16 CN11.12 U1.12(XROM)
XRSTN: C7.2 CN11.2 D3.1(A) R11.1 SW8.1 U1.2(XRSTN)
XRSTO: CN11.1 U1.1(XRSTO)
XSLEEVE: CN13.12 DZ7.1 Q6.3(DRAIN) R36.1 U1.46(XSLEEVE)
XSSCL: CN14.7 R23.2 U1.58(XSSCL)
XSSDA: CN14.8 R24.2 U1.59(XSSDA)
XVNEG_HPR/L: C15.1 CN14.1 U1.52(XVNEG_HPR/L)
XVREF: C11.1 C12.1 CN13.10 U1.44(XVREF)
XVRP_PAD: C9.1 C10.1 CN13.9 U1.43(XVRP_PAD)
N24422814: L19.1 Q7.3(D)
N24479617: C38.1 J2.2 L15.2
N24479627: C39.2 J2.3 L16.2
N24479978: L17.1 R59.1 R62.2
N24479982: L18.1 R60.1 R61.2
N24479994: C54.2 J4.3 L18.2
N24479996: C53.2 J4.2 L17.2
N24491129: C46.2 R46.1 R47.2
N24491353: J1.1 R34.2
N24491355: J1.6 R36.2
N24491403: C36.2 J1.2 R31.2
N24491405: C37.2 J1.3 R33.2
N24507827: Q7.1(G) R65.2 R66.2
N24578078: EC3.2 R37.2 R38.2 XC2.2
N24578080: EC2.2 R32.2 R35.2 XC1.2
N25105502: D9.1(ANODE) R64.2
N25375567: C18.1 CN14.16 L14.1 U1.67(VCC33)
N26098150: R40.2 R42.1 U2.3(-)
N26098213: C41.2 R42.2
N26098259: C44.2 R44.1 R45.2 U2.1(+)
N26105956: R48.2 R49.1 U4.3(-)
N26106001: C47.2 R49.2
N26106026: C49.2 R50.1 R52.2 U4.1(+)
N26109931: R51.2 R53.1 U3.3(-)
N26109976: C48.2 R53.2
N26110001: C51.2 R54.1 R55.2 U3.1(+)
N26135372: D4.1(ANODE) R12.2
N26135399: D5.1(ANODE) R13.2
N26135426: D6.1(ANODE) R14.2
N26135456: D7.1(ANODE) R17.2
N26135478: Q4.3(DRAIN) R18.2
N26135512: CN1.3 D8.1(A)
N26135514: C34.2 D8.2(K) Q4.1(GATE) R25.1
N26136173: Q1.3(D) R1.2
N26136192: Q2.3(D) R3.2
N26136204: Q3.3(D) R4.2
N26136236: C2.2 Q1.1(G) R7.2
N26136278: C3.2 Q2.1(G) R8.2
N26136320: C4.2 Q3.1(G) R9.2
N26138506: R5.2 USB1.A5(CC1)
N26138554: R6.2 USB1.B5(CC2)
N26161543: C6.1 CN12.11 L3.2 U1.28(VCC33)
N26170736: R2.1 R10.1 SW1.2 SW3.2 SW4.2 SW5.2
N26246836: D1.2(B) R3.1
N26246837: D1.3(G) R4.1
N26246838: D1.1(R) R1.1
N26246928: D1.4(VCC) L7.2
N27523953: R74.1 R75.2 U5.1(SD0/SA0)

Not connected (* = marked no-connect by the designer): H1 1(H)*; H2 1(H)*; H3 1(H)*; H4 1(H)*; J2 5*; J4 4 5* 6; U5 9(INT2)* 10(NC)* 11(NC)*; USB1 17(G)* 18(G)* A8(SBU1)* B8(SBU2)*

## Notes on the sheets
sheet 1
- Date
- Rev.
- Notice
- Create by
- 2025/04/14
- NEW CREATE (CM6646X2).
- Daniel Lee
- 2025/07/16
- v100
- 1.CM6646X1 and CM6646X2 are share the circuit.
- Daniel Lee
- 2. Volume control GPIO 9,10.
- 3. SPI LED GPIO 0,1 ; ARGB GPIO 0.
- 4. Add ARGB/SPI LED 5V.
- 5. JD add Pull low header.
- 6. PWM LED to USB5V/GND_EARTH.
- CM6646X1_CM6646X2_DemoBoard
sheet 2
- CM6646X1_CM6646X2_DemoBoard
sheet 3
- CM6646X1_CM6646X2_DemoBoard
sheet 4
- USB & Power
- 3 Color LED
- BUTTON
- R
- B
- G
- SW3
- MIC Mute
- SW5
- LDO OUT
- Chip reset
- Surround HP
- LDO OUT
- MIC Clipping
- Xear AI
- Volume control Indication
- SPI LED          ARGB
- ROM code mode mechanism
  and ESD solution
- normal _2,3
- ESD TVS close CM6646X1
- CM6646X1_CM6646X2_DemoBoard
sheet 5
- G-Sensor
sheet 6
- OPA power control
- ENCODER(VOLUME+/-)
- XGPIO_9 & 10:  Volume control (¶¶®ÉÄÁ±ÛÂà)
  HP vol. up / CSPK Vol. down (Banlance volume mode) ; CMA112 playback volume up (Master volume mode)
- XGPIO_9 & 10:  Volume control (°f®ÉÄÁ±ÛÂà)
  HP vol. down / CSPK Vol. up (Banlance mode) ; CMA112 playback volume down (Master volume mode)
- XGPIO_2:Volume control switch
  Banlance (Default) / Master volume mode switch
- CM6646X1_CM6646X2_DemoBoard
sheet 7
- 3-Ring Stereo Microphone Input
- COMBO JACK
- "XMICJD" is an output signal from OMTP/CTIA detection circuit
- For COMBO JACK (J1) application:
  C44,C46 was used for stereo recording (CBJ_MIC copy to C_MIC1 & XMIC2)
- 3-Ring stereo microphone inverter
- Combo jack microphone inverter
- Improve Headphone crosstalk performance
- Headphone Output
- Low Rds Mos.
- CM6646X1_CM6646X2_DemoBoard
